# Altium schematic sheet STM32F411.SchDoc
size A3; Author: Eylul Nihan Aycan; CompanyName: omlet*; SheetNumber: 1; SheetTotal: 1
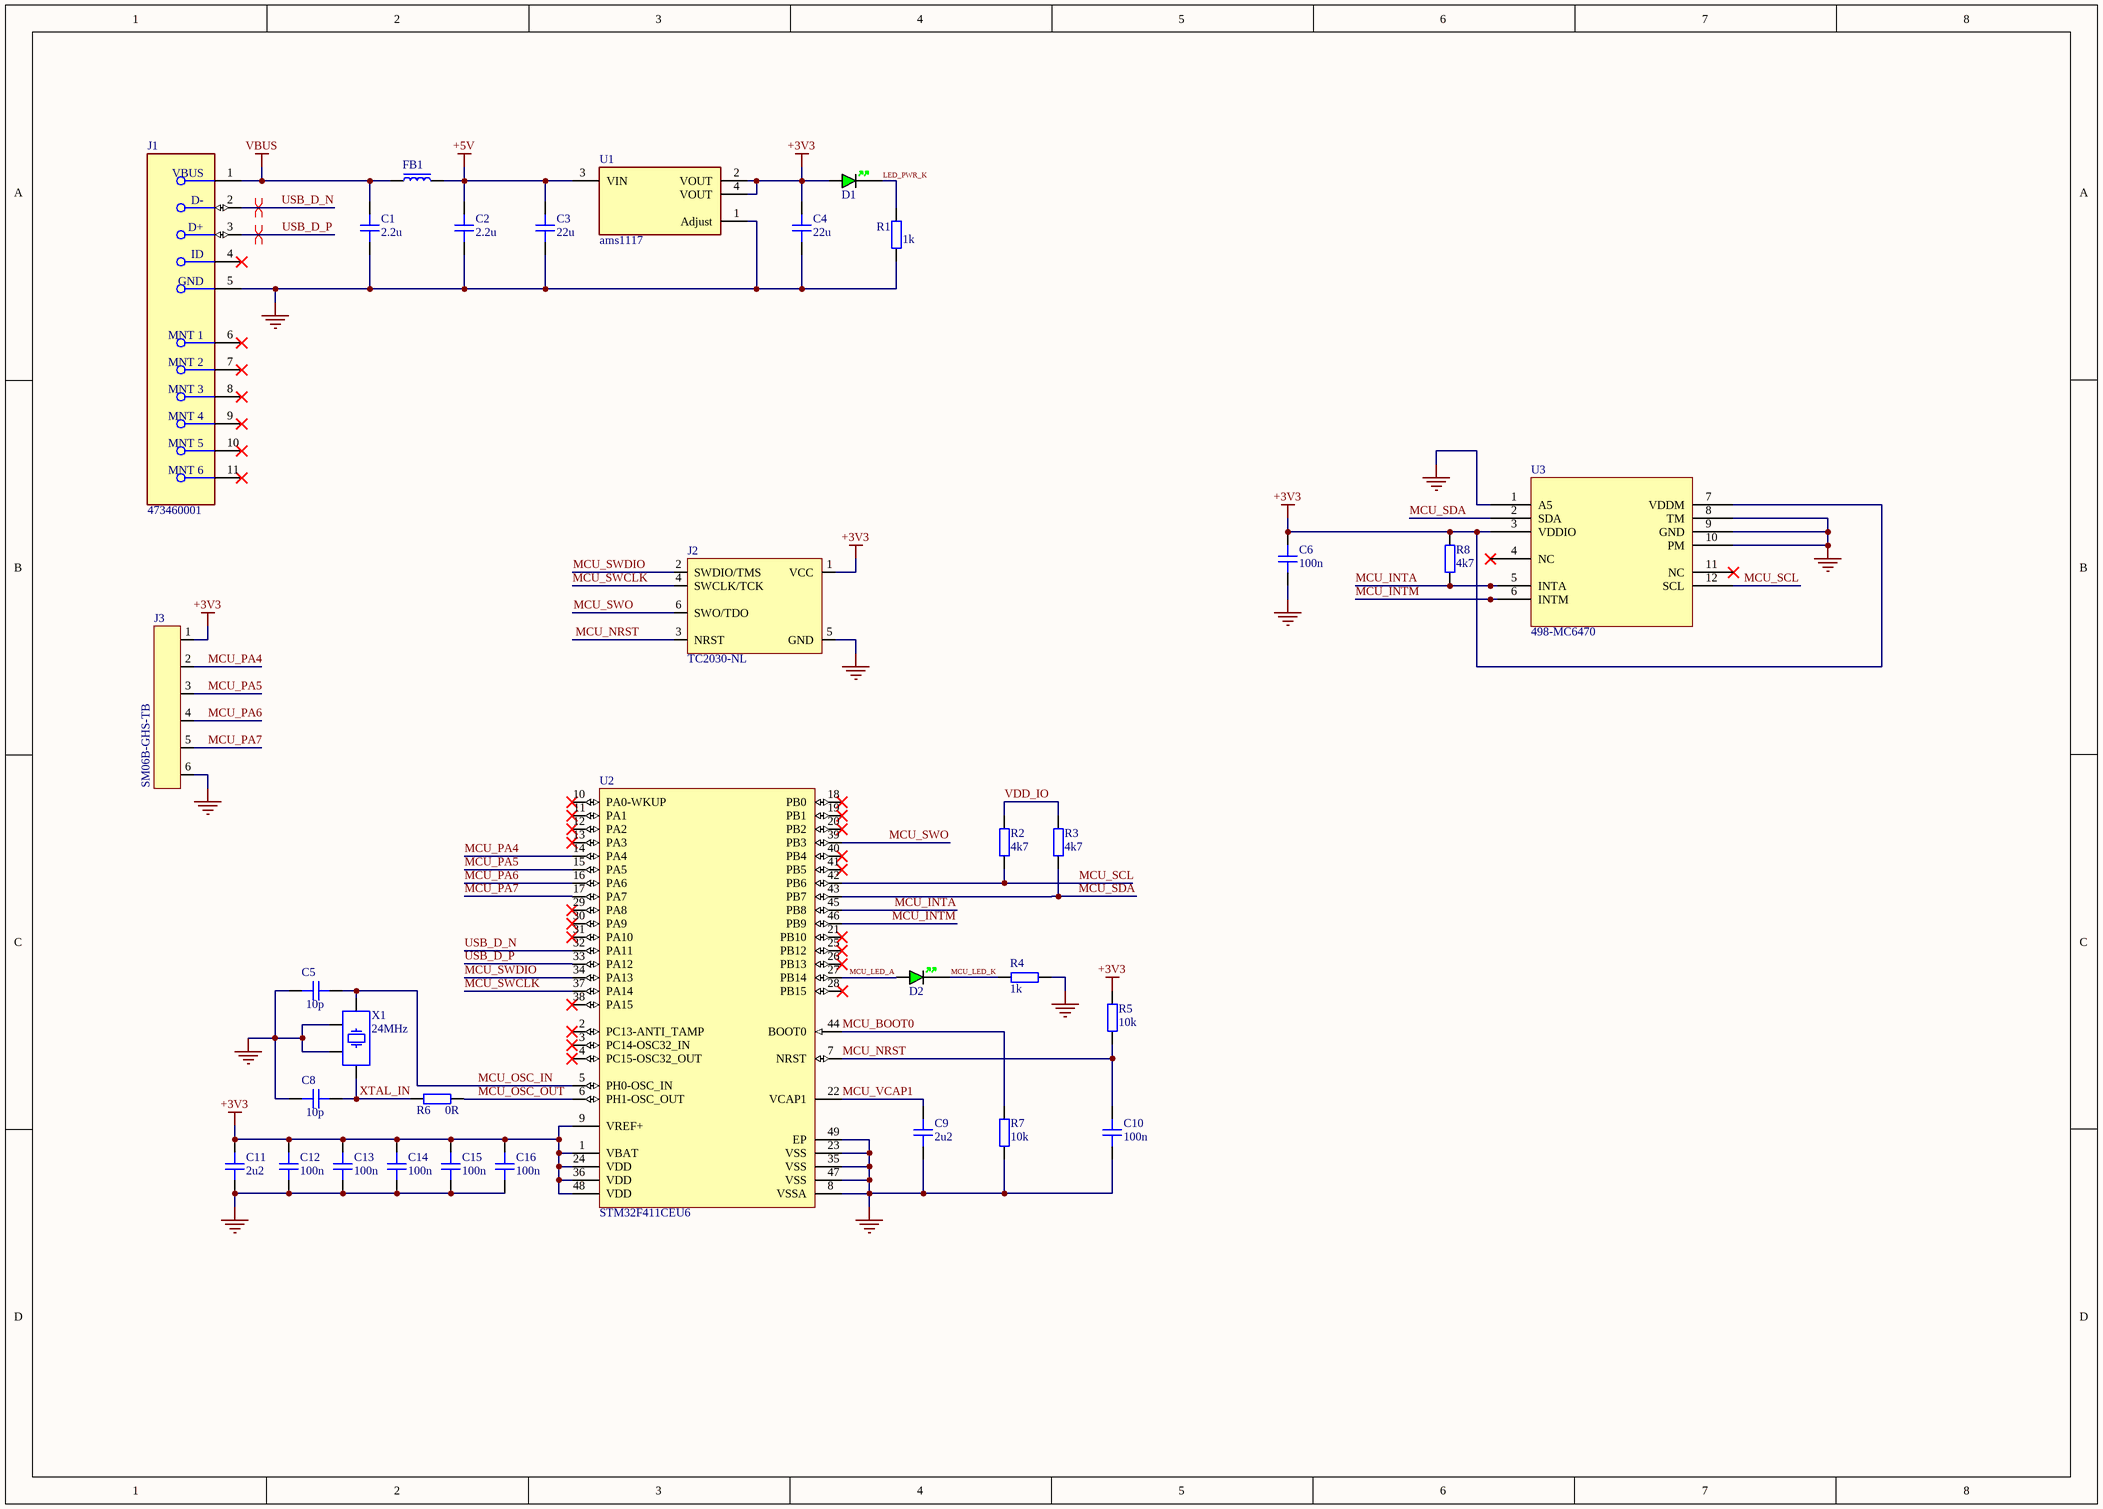
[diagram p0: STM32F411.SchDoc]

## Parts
C1  2.2u  [CAP_0603]
C2  2.2u  [CAP_0603]
C3  22u  [CAP_0805]
C4  22u  [CAP_0805]
C5  10p  [CAP_0402]
C6  100n  [CAP_0402]
C8  10p  [CAP_0402]
C9  2u2  [CAP_0603]
C10  100n  [CAP_0402]
C11  2u2  [CAP_0603]
C12  100n  [CAP_0402]
C13  100n  [CAP_0402]
C14  100n  [CAP_0402]
C15  100n  [CAP_0402]
C16  100n  [CAP_0402]
D1  GREEN  [LED_0402_GREEN]  (value not drawn)
D2  GREEN  [LED_0402_GREEN]  (value not drawn)
FB1  FB0603  [FB_0603]  (value not drawn)
J1  473460001  [FP-473460001-MFG]
J2  TC2030-NL  [TC2030-NL-FP]  (no BOM)
J3  SM06B-GHS-TB  [SM06B-GHS-TB]
R1  1k  [RES_0402]
R2  4k7  [RES_0402]
R3  4k7  [RES_0402]
R4  1k  [RES_0402]
R5  10k  [RES_0402]
R6  0R  [RES_0402]
R7  10k  [RES_0402]
R8  4k7  [RES_0402]
U1  ams1117  [FP-ams1117-IPC_C]
U2  STM32F411CEU6  [STM-UFQFPN48_L]
U3  498-MC6470  [MC6470]
X1  24MHz  [XTAL_3225]

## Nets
+3V3: C4.2 C6.2 C11.2 C12.2 C13.2 C14.2 C15.2 C16.2 D1.A J2.1(VCC) J3.1 R5.2 R8.2 U1.2(VOUT) U1.4(VOUT) U2.1(VBAT) U2.9(VREF+) U2.24(VDD) U2.36(VDD) U2.48(VDD) U3.3(VDDIO) U3.7(VDDM)
+5V: C2.2 C3.2 FB1.2 U1.3(VIN)
GND: C1.1 C2.1 C3.1 C4.1 C5.1 C6.1 C8.1 C9.1 C10.1 C11.1 C12.1 C13.1 C14.1 C15.1 C16.1 J1.5(GND) J2.5(GND) J3.6 R1.1 R4.2 R7.1 U1.1(Adjust) U2.8(VSSA) U2.23(VSS) U2.35(VSS) U2.47(VSS) U2.49(EP) U3.1(A5) U3.8(TM) U3.9(GND) U3.10(PM) X1.2 X1.4
VBUS: C1.2 FB1.1 J1.1(VBUS)
LED_PWR_K: D1.K R1.2
MCU_BOOT0: R7.2 U2.44(BOOT0)
MCU_INTA: R8.1 U2.45(PB8) U3.5(INTA)
MCU_INTM: U2.46(PB9) U3.6(INTM)
MCU_LED_A: D2.A U2.27(PB14)
MCU_LED_K: D2.K R4.1
MCU_NRST: C10.2 J2.3(NRST) R5.1 U2.7(NRST)
MCU_OSC_IN: C5.2 U2.5(PH0-OSC_IN) X1.1
MCU_OSC_OUT: R6.2 U2.6(PH1-OSC_OUT)
MCU_PA4: J3.2 U2.14(PA4)
MCU_PA5: J3.3 U2.15(PA5)
MCU_PA6: J3.4 U2.16(PA6)
MCU_PA7: J3.5 U2.17(PA7)
MCU_SCL: R2.1 U2.42(PB6) U3.12(SCL)
MCU_SDA: R3.1 U2.43(PB7) U3.2(SDA)
MCU_SWCLK: J2.4(SWCLK/TCK) U2.37(PA14)
MCU_SWDIO: J2.2(SWDIO/TMS) U2.34(PA13)
MCU_SWO: J2.6(SWO/TDO) U2.39(PB3)
MCU_VCAP1: C9.2 U2.22(VCAP1)
USB_D_N: J1.2(D-) U2.32(PA11)
USB_D_P: J1.3(D+) U2.33(PA12)
VDD_IO: R2.2 R3.2
XTAL_IN: C8.2 R6.1 X1.3

Not connected (* = marked no-connect by the designer): J1 4(ID)* 6(MNT_1)* 7(MNT_2)* 8(MNT_3)* 9(MNT_4)* 10(MNT_5)* 11(MNT_6)*; U2 2(PC13-ANTI_TAMP)* 3(PC14-OSC32_IN)* 4(PC15-OSC32_OUT)* 10(PA0-WKUP)* 11(PA1)* 12(PA2)* 13(PA3)* 18(PB0)* 19(PB1)* 20(PB2)* 21(PB10)* 25(PB12)* 26(PB13)* 28(PB15)* 29(PA8)* 30(PA9)* 31(PA10)* 38(PA15)* 40(PB4)* 41(PB5)*; U3 4(NC)* 11(NC)*

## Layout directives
differential pair; net class DIFF_USB: USB_D_N, USB_D_P

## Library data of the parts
C1 C2 C9 C11 = CAP_0603: Capacitor SMD 0603
C3 C4 = CAP_0805: Capacitor SMD 0805
C5 C6 C8 C10 C12-C16 = CAP_0402: Capacitor SMD 0402
D1 D2 = LED_0402_GREEN: LED 0402 GREEN SMD
FB1 = FB_0603: Ferrite Bead SMD 0603
J1 = CMP-2000-05246-2: CONN RCPT USB2.0 MICRO B SMD R/A; Manufacturer: Molex; Conn Orientation: Right Angle; Is Female: yes; Shielding: true; Pitch: 0.65mm; Number Of Contacts: 5; Voltage Rating: 30V; Current Rating: 1.8A
J2 = TC2030-NL: Tag-Connect No-Solder SWD Debug Connector (No Legs) DO NOT PLACE
J3 = SM06B-GHS-TB: Header Connector 6 Position 1.25MM Pitch SMD Horizontal JST GH
R1-R8 = RES_0402: Resistor SMD 0402
U1 = CMP-209535-000002-1: 1A LOW DROPOUT VOLTAGE REGULATOR
U2 = CMP-0243-00165-1: ARM Cortex-M4 32-bit MCU+FPU, 512 KB Flash, 128 KB RAM, 36 I/Os, 48-Pin UFQFPN, -40 to 85 degC, Tray; Operating Frequency(F) (Processor speed) (MHz): 100; FLASH Size (Prog) (kB): 512; Internal RAM Size (kB): 128; I/Os (High Current): 36; Supply Voltage(Vcc) min (V): 1.7
U3 = MC6470: IMUs - Inertial Measurement Units 8g, 14-Bit Output 6-Axis eCompass
X1 = TSX-3225_24.0000MF15X-AC: Crystal SMD 24MHz 10PPM 7pF 3225; Manufacturer: Epson; Manufacturer Part Number: TSX-3225 24.0000MF15X-AC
